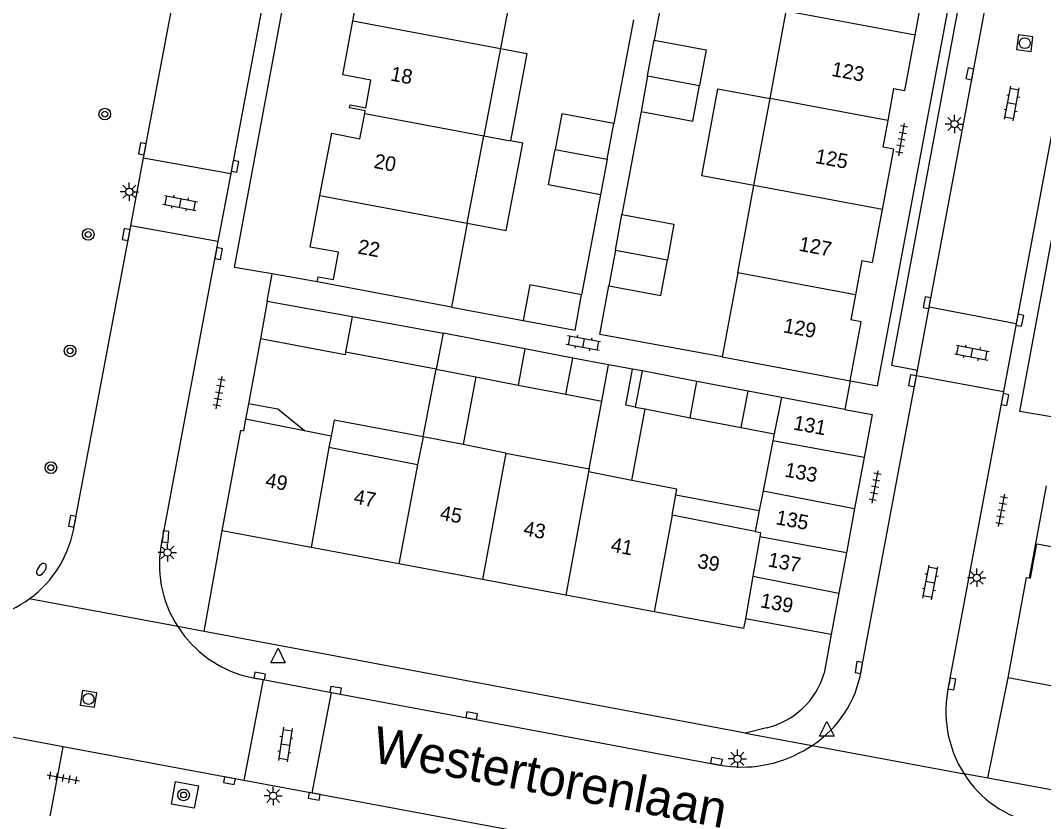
# Model space of a CAD drawing. Extents: x 131000 to 133014, y 396499 to 399001.
# Drawn here: x 131387.5 to 131457.5, y 397286.7 to 397340.6 of the extents above; entities that cross this region are included whole.
import ezdxf

# ---------------------------------------------------------------- set-up
doc = ezdxf.new("R2010")
doc.units = 0
for name, color, linetype in [('gg-afsc-erfafscheiding', 7, 'Continuous'), ('gg-afsc-muur', 7, 'Continuous'), ('gg-anno-huisnummerreeks BGT', 7, 'Continuous'), ('gg-anno-openbare ruimte label', 7, 'Continuous'), ('gg-bbg-bijgebouw', 7, 'Continuous'), ('gg-bbg-gedigitaliseerde bebouwing', 7, 'Continuous'), ('gg-bbg-gedigitaliseerde bijgebouw', 7, 'Continuous'), ('gg-bbg-hoofdgebouw', 7, 'Continuous'), ('gg-bbg-luifel en loopbrug', 7, 'Continuous'), ('gg-bbg-tussenscheiding', 7, 'Continuous'), ('gg-knt-verharding', 7, 'Continuous'), ('gg-knt-verharding nz', 7, 'Continuous'), ('gt-grn-weggrens', 7, 'Continuous'), ('gt-symb-boom', 7, 'Continuous'), ('gt-symb-brandkraan', 7, 'Continuous'), ('gt-symb-klinker verharding', 7, 'Continuous'), ('gt-symb-kolk', 7, 'Continuous'), ('gt-symb-lichtmast', 7, 'Continuous'), ('gt-symb-rioolschacht', 7, 'Continuous'), ('gt-symb-tegel verharding', 7, 'Continuous'), ('gt-symb-waterafsluiter', 7, 'Continuous')]:
    doc.layers.add(name, color=color, linetype=linetype)

# ---------------------------------------------------------------- blocks, each defined once
blk = doc.blocks.new('gt0-TEG1')
at = {"layer": 'gt-symb-tegel verharding'}
for p, q in [((-1.125, 0), (1.125, 0)), ((-0.9, -0.25), (-0.9, 0.25)), ((-0.45, -0.25), (-0.45, 0.25)), ((0, -0.25), (0, 0.25)), ((0.45, -0.25), (0.45, 0.25)), ((0.9, -0.25), (0.9, 0.25))]:
    blk.add_line(p, q, dxfattribs=at)
blk = doc.blocks.new('gt0-LMAST')
at = {"layer": 'gt-symb-lichtmast'}
for p, q in [((-0.182, 0.173), (-0.447, 0.438)), ((-0.005, 0.246), (-0.005, 0.621)), ((0.172, 0.173), (0.437, 0.438)), ((-0.255, -0.004), (-0.63, -0.004)), ((-0.182, -0.181), (-0.447, -0.446)), ((-0.005, -0.254), (-0.005, -0.629)), ((0.437, -0.446), (0.172, -0.181)), ((0.245, -0.004), (0.62, -0.004))]:
    blk.add_line(p, q, dxfattribs=at)
blk.add_circle((-0.005, -0.004), 0.25, dxfattribs=at)
blk = doc.blocks.new('gt0-KOLK')
at = {"layer": 'gt-symb-kolk'}
blk.add_lwpolyline([(0, 0), (0.375, 0), (0.375, 0.4), (-0.375, 0.4), (-0.375, 0), (0, 0)], dxfattribs=at)
blk = doc.blocks.new('gt0-KL1')
at = {"layer": 'gt-symb-klinker verharding'}
for p, q in [((-1.15, 0.3), (1.15, 0.3)), ((-1, -0.3), (-1, 0.3)), ((-0.5, 0.3), (-0.5, 0.45)), ((0, -0.3), (0, 0.3)), ((0.5, 0.3), (0.5, 0.45)), ((1, -0.3), (1, 0.3)), ((-1.15, -0.3), (1.15, -0.3)), ((-0.5, -0.45), (-0.5, -0.3)), ((0.5, -0.45), (0.5, -0.3))]:
    blk.add_line(p, q, dxfattribs=at)
blk = doc.blocks.new('gt0-RS')
at = {"layer": 'gt-symb-rioolschacht'}
blk.add_lwpolyline([(-0.5, -0.5), (0.5, -0.5), (0.5, 0.5), (-0.5, 0.5)], close=True, dxfattribs=at)
blk.add_circle((0, 0), 0.375, dxfattribs=at)
blk = doc.blocks.new('gt0-WAFSL')
at = {"layer": 'gt-symb-waterafsluiter'}
for p, q in [((-0.5, -0.333), (0, 0.667)), ((0, 0.667), (0.5, -0.333)), ((0.5, -0.333), (-0.5, -0.333))]:
    blk.add_line(p, q, dxfattribs=at)
blk = doc.blocks.new('gt0-BOOM')
at = {"layer": 'gt-symb-boom'}
for radius in [0.4, 0.2]:
    blk.add_circle((0, 0), radius, dxfattribs=at)
blk = doc.blocks.new('gt0-BR')
at = {"layer": 'gt-symb-brandkraan'}
for centre, radius, start, end in [((-0.244, 0), 0.206, 107.56694, 252.43307), ((0.599, -2.664), 3, 106.89205, 107.56694), ((0, -0.691), 0.938, 73.10799, 106.89205), ((-0.599, -2.664), 3, 72.43309, 73.10799), ((0.244, 0), 0.206, 287.56695, 72.43309), ((0.599, 2.664), 3, 252.43307, 253.10797), ((0, 0.691), 0.938, 253.10797, 286.89206), ((-0.599, 2.664), 3, 286.89206, 287.56695)]:
    blk.add_arc(centre, radius, start, end, dxfattribs=at)

msp = doc.modelspace()

# ---------------------------------------------------------------- linework, layer by layer
at = {"layer": 'gg-afsc-erfafscheiding'}
for p, q in [((131431.515, 397342.809), (131430.863, 397339.278)), ((131429.443, 397340.666), (131428.109, 397333.575)), ((131429.964, 397334.407), (131428.659, 397327.34)), ((131427.192, 397328.701), (131425.901, 397321.857)), ((131416.984, 397321.012), (131421.888, 397320.086)), ((131430.044, 397316.642), (131429.378, 397316.763))]:
    msp.add_line(p, q, dxfattribs=at)
msp.add_lwpolyline([(131435.53, 397317.59), (131427.144, 397319.139), (131427.759, 397322.469)], dxfattribs=at)
at = {"layer": 'gg-afsc-muur'}
for p, q in [((131403.911, 397318.826), (131403.087, 397314.39)), ((131457.714, 397308.769), (131456.536, 397302.463))]:
    msp.add_line(p, q, dxfattribs=at)
at = {"layer": 'gg-bbg-bijgebouw'}
for p, q in [((131404.366, 397321.41), (131403.911, 397318.826)), ((131445.242, 397310.703), (131444.592, 397307.207)), ((131444.592, 397307.207), (131444.029, 397304.18)), ((131444.029, 397304.18), (131443.517, 397301.424)), ((131443.517, 397301.424), (131442.99, 397298.59)), ((131442.99, 397298.59), (131437.11, 397299.67))]:
    msp.add_line(p, q, dxfattribs=at)
msp.add_lwpolyline([(131443.922, 397314.003), (131445.79, 397313.65), (131445.242, 397310.703)], dxfattribs=at)
at = {"layer": 'gg-bbg-gedigitaliseerde bebouwing'}
for p, q in [((131421.475, 397344.688), (131420.341, 397338.708)), ((131420.341, 397338.708), (131419.206, 397332.727)), ((131418.072, 397326.748), (131419.206, 397332.727)), ((131418.072, 397326.748), (131416.984, 397321.012)), ((131416.984, 397321.012), (131407.8, 397322.74)), ((131402.889, 397313.325), (131402.744, 397312.541)), ((131406.919, 397312.533), (131402.889, 397313.325)), ((131408.745, 397312.174), (131406.919, 397312.533)), ((131408.745, 397312.174), (131408.598, 397311.388)), ((131415.04, 397312.129), (131414.659, 397310.194)), ((131417.778, 397311.59), (131415.04, 397312.129)), ((131414.659, 397310.194), (131408.598, 397311.388)), ((131420.712, 397311.012), (131417.778, 397311.59)), ((131420.712, 397311.012), (131426.414, 397309.938)), ((131426.414, 397309.938), (131426.374, 397309.724)), ((131429.328, 397309.142), (131426.374, 397309.724)), ((131432.088, 397306.762), (131432.347, 397308.148)), ((131437.775, 397305.642), (131432.088, 397306.762))]:
    msp.add_line(p, q, dxfattribs=at)
msp.add_lwpolyline([(131432.347, 397308.148), (131432.419, 397308.533), (131429.328, 397309.142)], dxfattribs=at)
at = {"layer": 'gg-bbg-gedigitaliseerde bijgebouw'}
for p, q in [((131430.415, 397336.842), (131430.863, 397339.278)), ((131430.415, 397336.842), (131429.964, 397334.407)), ((131427.653, 397331.138), (131428.109, 397333.575)), ((131427.653, 397331.138), (131427.192, 397328.701)), ((131428.211, 397324.904), (131428.659, 397327.34)), ((131428.211, 397324.904), (131427.759, 397322.469)), ((131404.366, 397321.41), (131410.177, 397320.366)), ((131410.177, 397320.366), (131416.409, 397319.213)), ((131415.933, 397316.762), (131409.74, 397317.921)), ((131425.304, 397317.504), (131422.017, 397318.142)), ((131424.824, 397315.035), (131425.304, 397317.504)), ((131415.933, 397316.762), (131418.647, 397316.235)), ((131418.647, 397316.235), (131421.561, 397315.669)), ((131430.044, 397316.642), (131429.564, 397314.16)), ((131433.793, 397315.917), (131430.044, 397316.642)), ((131421.561, 397315.669), (131424.824, 397315.035)), ((131437.292, 397315.241), (131433.793, 397315.917)), ((131436.812, 397312.76), (131437.292, 397315.241)), ((131439.582, 397314.823), (131439.092, 397312.333)), ((131443.922, 397314.003), (131439.582, 397314.823)), ((131429.564, 397314.16), (131430.243, 397314.029)), ((131430.243, 397314.029), (131433.33, 397313.433)), ((131433.33, 397313.433), (131436.812, 397312.76)), ((131439.092, 397312.333), (131438.997, 397311.851)), ((131438.997, 397311.851), (131438.324, 397308.432)), ((131438.324, 397308.432), (131438.058, 397307.08)), ((131438.058, 397307.08), (131437.775, 397305.642))]:
    msp.add_line(p, q, dxfattribs=at)
for points in [[(131430.863, 397339.278), (131434.423, 397338.623), (131433.975, 397336.185)], [(131429.964, 397334.407), (131433.523, 397333.747), (131433.975, 397336.185)], [(131428.109, 397333.575), (131424.551, 397334.242), (131424.095, 397331.807)], [(131427.192, 397328.701), (131423.635, 397329.373), (131424.095, 397331.807)], [(131428.659, 397327.34), (131432.219, 397326.685), (131431.77, 397324.247)], [(131427.759, 397322.469), (131431.318, 397321.809), (131431.77, 397324.247)], [(131425.901, 397321.857), (131422.342, 397322.521), (131421.888, 397320.086)], [(131421.888, 397320.086), (131425.446, 397319.42), (131425.901, 397321.857)], [(131422.017, 397318.142), (131418.328, 397318.859), (131416.409, 397319.213)], [(131409.74, 397317.921), (131409.708, 397317.74), (131403.911, 397318.826)]]:
    msp.add_lwpolyline(points, dxfattribs=at)
at = {"layer": 'gg-bbg-hoofdgebouw'}
for p, q in [((131438.798, 397335.294), (131439.9, 397341.262)), ((131447.262, 397335.981), (131446.858, 397333.79)), ((131437.696, 397329.324), (131438.798, 397335.294)), ((131446.858, 397333.79), (131446.52, 397331.96)), ((131436.594, 397323.356), (131437.696, 397329.324)), ((131445.085, 397324.19), (131444.654, 397321.852)), ((131436.594, 397323.356), (131435.53, 397317.59)), ((131444.654, 397321.852), (131444.337, 397320.134)), ((131435.53, 397317.59), (131444.29, 397315.955)), ((131407.389, 397304.537), (131401.28, 397305.68)), ((131413.381, 397303.416), (131407.389, 397304.537)), ((131419.108, 397302.344), (131413.381, 397303.416)), ((131424.824, 397301.275), (131419.108, 397302.344)), ((131456.536, 397302.463), (131456.624, 397302.446)), ((131430.855, 397300.146), (131424.824, 397301.275)), ((131461.159, 397294.491), (131455.1, 397295.63))]:
    msp.add_line(p, q, dxfattribs=at)
for points in [[(131410.237, 397340.601), (131411.006, 397344.698), (131412.942, 397344.335), (131413.298, 397346.234)], [(131448.728, 397339.616), (131449.473, 397343.622), (131448.699, 397343.766)], [(131411.045, 397334.256), (131411.081, 397334.445), (131410.004, 397334.644), (131410.043, 397334.85), (131411.119, 397334.648), (131411.475, 397336.541), (131409.543, 397336.903), (131410.237, 397340.601)], [(131447.262, 397335.981), (131448.025, 397335.839), (131448.728, 397339.616)], [(131407.983, 397328.638), (131408.789, 397332.92), (131410.721, 397332.534), (131411.045, 397334.256)], [(131446.5, 397327.682), (131447.272, 397331.82), (131446.52, 397331.96)], [(131407.8, 397322.74), (131407.863, 397323.079), (131408.915, 397322.887), (131409.258, 397324.763), (131407.318, 397325.107), (131407.983, 397328.638)], [(131445.085, 397324.19), (131445.823, 397324.052), (131446.5, 397327.682)], [(131444.29, 397315.955), (131445.045, 397320.002), (131444.337, 397320.134)], [(131401.28, 397305.68), (131402.556, 397312.578), (131402.744, 397312.541)], [(131456.624, 397302.446), (131457.066, 397304.804), (131462.789, 397303.775), (131462.717, 397303.392)], [(131455.1, 397295.63), (131456.369, 397302.494), (131456.536, 397302.463)], [(131437.11, 397299.67), (131436.98, 397299), (131430.855, 397300.146)]]:
    msp.add_lwpolyline(points, dxfattribs=at)
at = {"layer": 'gg-bbg-luifel en loopbrug'}
for p, q in [((131419.206, 397332.727), (131421.027, 397332.384)), ((131427.738, 397317.061), (131425.304, 397317.504)), ((131427.276, 397314.576), (131427.738, 397317.061)), ((131429.378, 397316.763), (131427.738, 397317.061)), ((131415.04, 397312.129), (131415.933, 397316.762)), ((131418.647, 397316.235), (131417.778, 397311.59)), ((131424.824, 397315.035), (131427.276, 397314.576)), ((131439.582, 397314.823), (131437.292, 397315.241)), ((131403.087, 397314.39), (131402.889, 397313.325)), ((131426.414, 397309.938), (131427.276, 397314.576)), ((131429.328, 397309.142), (131430.243, 397314.029)), ((131436.812, 397312.76), (131439.092, 397312.333)), ((131432.347, 397308.148), (131438.058, 397307.08))]:
    msp.add_line(p, q, dxfattribs=at)
for points in [[(131420.341, 397338.708), (131422.153, 397338.367), (131421.027, 397332.384)], [(131437.696, 397329.324), (131434.127, 397329.984), (131435.232, 397335.954), (131438.798, 397335.294)], [(131418.072, 397326.748), (131420.737, 397326.246), (131421.863, 397332.227), (131421.027, 397332.384)], [(131429.564, 397314.16), (131428.914, 397314.282), (131429.378, 397316.763)], [(131406.919, 397312.533), (131405.106, 397314.016), (131403.087, 397314.39)], [(131415.04, 397312.129), (131408.95, 397313.269), (131408.745, 397312.174)]]:
    msp.add_lwpolyline(points, dxfattribs=at)
at = {"layer": 'gg-bbg-tussenscheiding'}
for p, q in [((131448.728, 397339.616), (131439.9, 397341.262)), ((131410.237, 397340.601), (131420.341, 397338.708)), ((131430.415, 397336.842), (131433.975, 397336.185)), ((131446.858, 397333.79), (131438.798, 397335.294)), ((131411.045, 397334.256), (131419.206, 397332.727)), ((131424.095, 397331.807), (131427.653, 397331.138)), ((131446.5, 397327.682), (131437.696, 397329.324)), ((131407.983, 397328.638), (131418.072, 397326.748)), ((131428.211, 397324.904), (131431.77, 397324.247)), ((131444.654, 397321.852), (131436.594, 397323.356)), ((131410.177, 397320.366), (131409.74, 397317.921)), ((131416.409, 397319.213), (131415.933, 397316.762)), ((131422.017, 397318.142), (131421.561, 397315.669)), ((131433.33, 397313.433), (131433.793, 397315.917)), ((131408.598, 397311.388), (131407.389, 397304.537)), ((131445.242, 397310.703), (131438.997, 397311.851)), ((131420.712, 397311.012), (131419.108, 397302.344)), ((131414.659, 397310.194), (131413.381, 397303.416)), ((131426.374, 397309.724), (131424.824, 397301.275)), ((131438.324, 397308.432), (131444.592, 397307.207)), ((131432.088, 397306.762), (131430.855, 397300.146)), ((131438.104, 397305.285), (131437.624, 397302.574)), ((131444.029, 397304.18), (131438.104, 397305.285)), ((131437.624, 397302.574), (131437.11, 397299.67)), ((131437.624, 397302.574), (131443.517, 397301.424))]:
    msp.add_line(p, q, dxfattribs=at)
msp.add_lwpolyline([(131437.775, 397305.642), (131438.154, 397305.568), (131438.104, 397305.285)], dxfattribs=at)
at = {"layer": 'gg-knt-verharding'}
for p, q in [((131411.759, 397382.968), (131401.871, 397330.153)), ((131464.728, 397368.535), (131455.65, 397319.869)), ((131395.903, 397331.22), (131399.917, 397352.547)), ((131395.027, 397326.564), (131395.903, 397331.22)), ((131395.903, 397331.22), (131401.871, 397330.153)), ((131401.871, 397330.153), (131400.999, 397325.495)), ((131391.18, 397306.12), (131395.027, 397326.564)), ((131400.999, 397325.495), (131395.027, 397326.564)), ((131400.999, 397325.495), (131397.16, 397304.99)), ((131404.366, 397321.41), (131404.717, 397323.273)), ((131407.8, 397322.74), (131404.717, 397323.273)), ((131455.65, 397319.869), (131449.7, 397320.996)), ((131455.65, 397319.869), (131454.786, 397315.238)), ((131445.04, 397296.1), (131448.827, 397316.332)), ((131448.827, 397316.332), (131448.892, 397316.681)), ((131448.827, 397316.332), (131454.786, 397315.238)), ((131444.29, 397315.955), (131443.922, 397314.003)), ((131454.786, 397315.238), (131451.03, 397295.1)), ((131400.05, 397298.79), (131401.28, 397305.68)), ((131437.13, 397291.84), (131400.05, 397298.79)), ((131442.99, 397298.59), (131442.51, 397295.94)), ((131404.095, 397295.495), (131402.769, 397288.599)), ((131403.64, 397295.58), (131404.095, 397295.495)), ((131404.095, 397295.495), (131408.762, 397294.623)), ((131453.72, 397288.74), (131455.1, 397295.63)), ((131407.454, 397287.727), (131408.762, 397294.623)), ((131408.762, 397294.623), (131435.37, 397289.65)), ((131390.403, 397290.902), (131385.335, 397291.846)), ((131438.56, 397292.2), (131437.13, 397291.84)), ((131441.08, 397290.63), (131441.69, 397290.988)), ((131402.769, 397288.599), (131390.403, 397290.902)), ((131452.082, 397289.046), (131452.3, 397288.72)), ((131407.454, 397287.727), (131402.769, 397288.599)), ((131433.86, 397282.81), (131407.454, 397287.727))]:
    msp.add_line(p, q, dxfattribs=at)
for points in [[(131404.717, 397323.273), (131402.13, 397323.72), (131414.258, 397389.07)], [(131458.565, 397313.268), (131458.59, 397313.4), (131455.91, 397313.86), (131466.89, 397373.12)], [(131456.828, 397369.134), (131447.108, 397317.027), (131448.892, 397316.681)], [(131444.29, 397315.955), (131446.155, 397315.605), (131453.84, 397356.71), (131453.28, 397356.85)], [(131398.241, 397299.129), (131398.709, 397298.484), (131399.24, 397297.89)], [(131490.78, 397288.92), (131489.47, 397282.17), (131453.72, 397288.74)], [(131399.361, 397286.691), (131397.822, 397286.977), (131398.098, 397288.517), (131399.66, 397288.227), (131399.361, 397286.691)]]:
    msp.add_lwpolyline(points, dxfattribs=at)
for centre, radius, start, end in [((131383.486, 397307.319), 7.787, 306.15411, 351.13993), ((131404.768, 397303.363), 7.78, 167.92888, 212.97145), ((131383.485, 397307.323), 7.79, 264.36623, 306.14762), ((131404.835, 397303.202), 7.715, 223.51314, 261.08791), ((131437.313, 397297.473), 5.418, 283.30355, 343.56794), ((131437.551, 397297.354), 7.593, 303.03065, 350.49403), ((131458.852, 397293.341), 8.017, 167.32399, 212.39164), ((131436.897, 397297.875), 8.366, 259.47939, 299.99805), ((131458.375, 397292.974), 7.417, 214.99983, 261.97564)]:
    msp.add_arc(centre, radius, start, end, dxfattribs=at)
at = {"layer": 'gg-knt-verharding nz'}
for p, q in [((131449.7, 397320.996), (131458.65, 397368.817)), ((131448.892, 397316.681), (131449.7, 397320.996))]:
    msp.add_line(p, q, dxfattribs=at)
at = {"layer": 'gt-grn-weggrens'}
for p, q in [((131398.241, 397299.129), (131388.08, 397301.032)), ((131400.05, 397298.79), (131398.241, 397299.129)), ((131437.13, 397291.84), (131441.69, 397290.988)), ((131441.69, 397290.988), (131452.082, 397289.046)), ((131389.41, 397285.65), (131390.403, 397290.902)), ((131453.72, 397288.74), (131452.082, 397289.046))]:
    msp.add_line(p, q, dxfattribs=at)

# ---------------------------------------------------------------- block references
at = {"layer": 'gt-symb-boom'}
for p in [(131393.25, 397334.222), (131392.112, 397325.982), (131390.872, 397318.01), (131389.555, 397310.012), (131398.644, 397287.601)]:
    msp.add_blockref('gt0-BOOM', p, dxfattribs=at)
at = {"layer": 'gt-symb-brandkraan', "rotation": 55.960475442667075}
msp.add_blockref('gt0-BR', (131388.907, 397303.048), dxfattribs=at)
at = {"layer": 'gt-symb-klinker verharding'}
for p, rotation in [((131455.362, 397334.942), 79.45426563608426), ((131398.415, 397328.132), -10.837910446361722), ((131426.014, 397318.534), 169.39794170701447), ((131452.629, 397317.894), -10.837910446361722), ((131449.772, 397302.156), 79.39794170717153), ((131405.607, 397291.055), -98.62422873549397)]:
    msp.add_blockref('gt0-KL1', p, dxfattribs=dict(at, rotation=rotation))
at = {"layer": 'gt-symb-kolk'}
for p, rotation in [((131452.682, 397336.94), 78.34159837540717), ((131396.015, 397331.807), 79.6900296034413), ((131401.97, 397330.684), -100.54573436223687), ((131394.91, 397325.939), 79.51061018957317), ((131400.85, 397324.71), -100.83791044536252), ((131449.75, 397321.272), 80.38697413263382), ((131455.702, 397320.145), -101.88275885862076), ((131448.75, 397315.921), 79.34163849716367), ((131454.688, 397314.711), -100.71464389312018), ((131391.218, 397306.306), 80.03848340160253), ((131397.212, 397305.305), -94.99208116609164), ((131445.076, 397296.292), 80.44347238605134), ((131403.813, 397295.546), -10.602058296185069), ((131451.055, 397295.235), -101.1863292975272), ((131409.022, 397294.574), -9.613025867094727), ((131418.332, 397292.834), -10.36632260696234), ((131435.095, 397289.701), -10.602058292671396), ((131401.821, 397288.776), 169.4542656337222), ((131407.619, 397287.697), 169.69002960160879)]:
    msp.add_blockref('gt0-KOLK', p, dxfattribs=dict(at, rotation=rotation))
at = {"layer": 'gt-symb-lichtmast'}
for p in [(131451.432, 397333.545), (131394.933, 397328.907), (131397.543, 397304.208), (131452.957, 397302.475), (131436.572, 397290.083), (131404.783, 397287.54)]:
    msp.add_blockref('gt0-LMAST', p, dxfattribs=at)
at = {"layer": 'gt-symb-rioolschacht'}
for p, rotation in [((131456.244, 397339.078), 82.53402593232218), ((131392.135, 397294.176), 171.25383774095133)]:
    msp.add_blockref('gt0-RS', p, dxfattribs=dict(at, rotation=rotation))
at = {"layer": 'gt-symb-tegel verharding'}
for p, rotation in [((131447.812, 397332.481), 79.51061019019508), ((131401.082, 397315.144), 79.39794170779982), ((131445.997, 397308.696), 79.39794170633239), ((131454.66, 397307.083), 79.45426563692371), ((131390.4, 397288.765), -10.54573436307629)]:
    msp.add_blockref('gt0-TEG1', p, dxfattribs=dict(at, rotation=rotation))
at = {"layer": 'gt-symb-waterafsluiter'}
for p in [(131405.109, 397296.976), (131442.69, 397291.956)]:
    msp.add_blockref('gt0-WAFSL', p, dxfattribs=at)

# ---------------------------------------------------------------- texts
at = {"layer": 'gg-anno-huisnummerreeks BGT'}
for s, rotation, p in [('18', 349.4, (131412.751, 397336.525)), ('123', 349.5, (131442.958, 397336.844)), ('125', 349.5, (131441.842, 397330.879)), ('20', 349.3, (131411.622, 397330.544)), ('22', 349.3, (131410.519, 397324.684)), ('127', 349.5, (131440.721, 397324.871)), ('129', 349.5, (131439.657, 397319.287)), ('131', 349.5, (131440.346, 397312.628)), ('133', 349.5, (131439.747, 397309.406)), ('49', 349.4, (131404.196, 397308.696)), ('47', 349.4, (131410.244, 397307.564)), ('45', 349.4, (131416.143, 397306.46)), ('135', 349.5, (131439.141, 397306.145)), ('43', 349.4, (131421.864, 397305.39)), ('41', 349.4, (131427.843, 397304.271)), ('39', 349.4, (131433.779, 397303.16)), ('137', 349.5, (131438.603, 397303.253)), ('139', 349.5, (131438.084, 397300.458))]:
    msp.add_text(s, height=1, rotation=rotation, dxfattribs=at).set_placement(p)
at = {"layer": 'gg-anno-openbare ruimte label'}
msp.add_text('Westertorenlaan', height=2.5, rotation=349.3, dxfattribs=at).set_placement((131411.47, 397289.871))

doc.saveas('drawing.dxf')
